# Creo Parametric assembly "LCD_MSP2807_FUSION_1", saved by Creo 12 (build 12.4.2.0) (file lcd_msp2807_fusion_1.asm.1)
Units: Custom; MM, KILOGRAM, SECS

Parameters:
  PTC_WM_ITERATION = "0"
  PTC_WM_VERSION = "-.0"
  PTC_WM_LIFECYCLE_STATE = "In Work"
  PTC_WM_LIFECYCLE = "MO_CADDocument"
  PTC_WM_CREATED_BY = "Maximilian Roepper (Z0017RMS: MO)"
  PTC_WM_CREATED_ON = "18-Sep-26 11:36:42 AM"
  PTC_WM_MODIFIED_BY = "Maximilian Roepper (Z0017RMS: MO)"
  PTC_WM_MODIFIED_ON = "18-Sep-26 11:36:46 AM"
  PDMLINKNUMBER = "PDM000071455089"
  PTC_WM_NUMBER = "PDM000071455089"

Other parameters: WEIGHT, WEIGHT_FACTOR, WEIGHT_ADD, MC_ERRORS, SUPPLIER

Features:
  1. coordinate system
  2. imported feature
  3. component "2_8__LCD_MSP2807_1"

Other named items: DRW_VIEW_ORG, ROUGH-GROB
